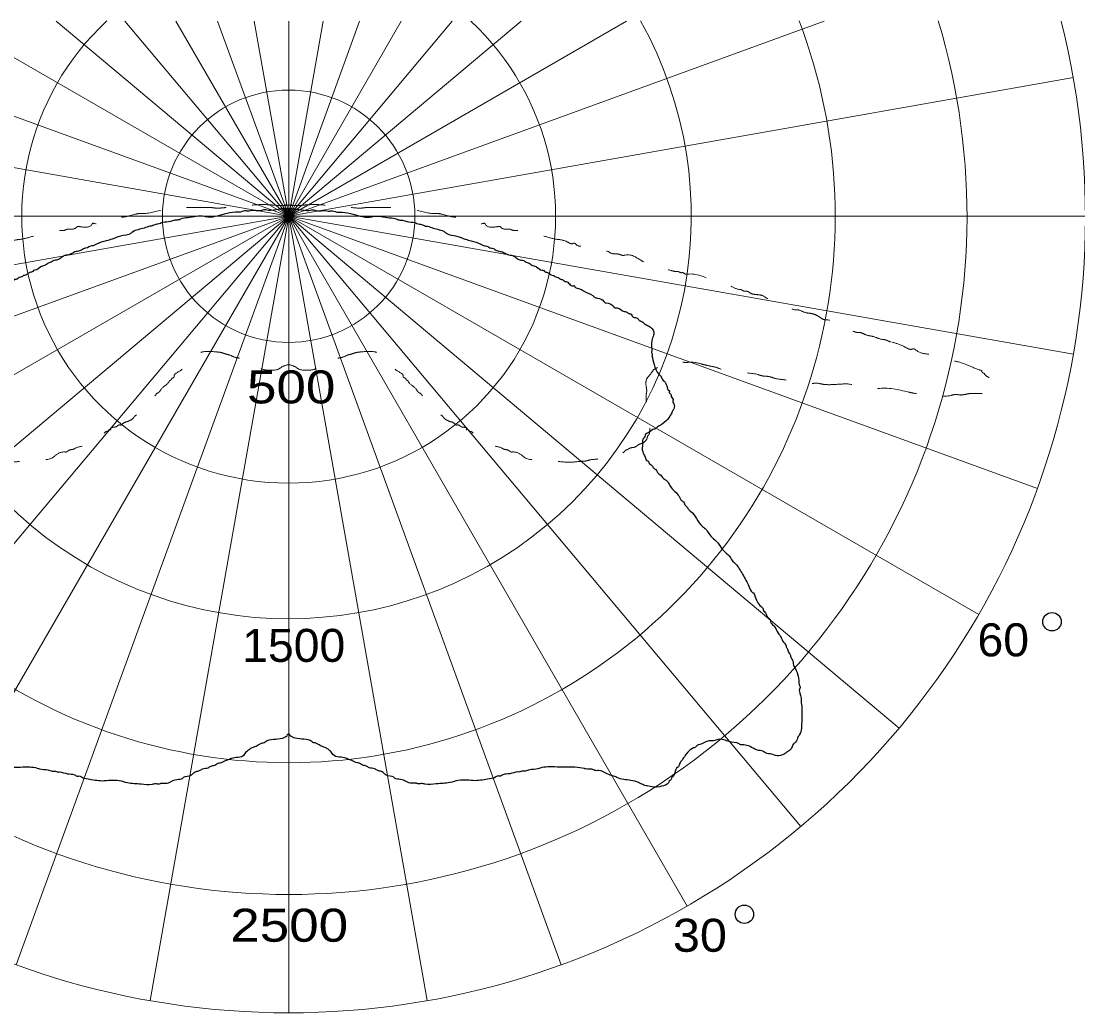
# Model space of a CAD drawing. Extents: x -39.6 to 16.1, y -17.6 to 34.
# Drawn here: x 8.272 to 12.275, y 27.093 to 30.849 of the extents above; entities that cross this region are included whole.
import ezdxf
from ezdxf.enums import TextEntityAlignment as Align

# ---------------------------------------------------------------- set-up
doc = ezdxf.new("R2010")
doc.units = 0
doc.header["$LTSCALE"] = 0.05
doc.linetypes.add('MEDIUM_DASHED', pattern=[4.5, 3, -1.5])
doc.layers.add('1', color=7, linetype='Continuous', lineweight=13)

msp = doc.modelspace()

# ---------------------------------------------------------------- linework, layer by layer
at = {"layer": '1'}
for p, q in [((9.28579, 30.11042), (7.25679, 30.84942)), ((9.28579, 30.11042), (8.00579, 30.84942)), ((9.28579, 30.11042), (8.40479, 30.84942)), ((9.28579, 30.11042), (8.66579, 30.84942)), ((9.28579, 30.11042), (8.85879, 30.84942)), ((9.28579, 30.11042), (9.01679, 30.84942)), ((9.28579, 30.11042), (9.15479, 30.84942)), ((9.28579, 30.11042), (11.31379, 30.84942)), ((9.28579, 30.11042), (10.56479, 30.84942)), ((9.28579, 30.11042), (10.16579, 30.84942)), ((9.28579, 30.11042), (9.90479, 30.84942)), ((9.28579, 30.11042), (9.71179, 30.84942)), ((9.28579, 30.11042), (9.55379, 30.84942)), ((9.28579, 30.11042), (9.41579, 30.84942)), ((9.28579, 30.11042), (9.28579, 30.84942)), ((9.28579, 30.11042), (6.31379, 30.63542)), ((9.28579, 30.11042), (12.25779, 30.63542)), ((9.28579, 30.11042), (6.26779, 30.11142)), ((6.26879, 30.11042), (12.30279, 30.11042)), ((9.28579, 30.11042), (6.31379, 29.58742)), ((9.28579, 30.11042), (6.44979, 29.07942)), ((9.28579, 30.11042), (6.67179, 28.60242)), ((9.28579, 30.11042), (6.97379, 28.17142)), ((9.28579, 30.11042), (7.34579, 27.79942)), ((9.28579, 30.11042), (7.77679, 27.49742)), ((9.28579, 30.11042), (8.25379, 27.27542)), ((9.28579, 30.11042), (8.76179, 27.13942)), ((9.28579, 30.11042), (12.30379, 30.11142)), ((9.28579, 30.11042), (9.28579, 27.09342)), ((9.28579, 30.11042), (9.80979, 27.13942)), ((9.28579, 30.11042), (10.31779, 27.27542)), ((9.28579, 30.11042), (10.79479, 27.49742)), ((9.28579, 30.11042), (11.22579, 27.79942)), ((9.28579, 30.11042), (11.59779, 28.17142)), ((9.28579, 30.11042), (11.89979, 28.60242)), ((9.28579, 30.11042), (12.12179, 29.07942)), ((9.28579, 30.11042), (12.25779, 29.58742))]:
    msp.add_line(p, q, dxfattribs=at)
msp.add_circle((9.28579, 30.11042), 0.47803, dxfattribs=at)
at = {"layer": '1', "lineweight": 25}
for centre in [(12.17679, 28.57442), (11.01179, 27.46642)]:
    msp.add_circle(centre, 0.03489, dxfattribs=at)
at = {"layer": '1'}
for radius, start, end in [(3.01743, 165.81631, 14.18369), (2.56899, 163.27297, 16.73988), (2.06984, 159.06789, 20.94201), (1.5247, 150.99651, 29.03998), (1.011, 132.95316, 46.96389)]:
    msp.add_arc((9.28579, 30.11042), radius, start, end, dxfattribs=at)
at = {"layer": '1', "linetype": 'MEDIUM_DASHED'}
for points in [[(9.29779, 30.15342), (9.27279, 30.15142), (9.24179, 30.15142), (9.21679, 30.15342), (9.15779, 30.15342), (9.12579, 30.15042), (9.10679, 30.15042), (9.04679, 30.14342), (9.00979, 30.14142), (8.99079, 30.14342), (8.95279, 30.14342), (8.87979, 30.14342), (8.84379, 30.13942), (8.81879, 30.13642), (8.73379, 30.12042), (8.71779, 30.12042), (8.70679, 30.11842), (8.65979, 30.10742), (8.64479, 30.10642), (8.59179, 30.09542), (8.55179, 30.08242), (8.54179, 30.08242), (8.54079, 30.08042), (8.49879, 30.07042), (8.48279, 30.06942), (8.48079, 30.06742), (8.45379, 30.06142), (8.44779, 30.06142), (8.44079, 30.05842), (8.42079, 30.05642), (8.36379, 30.04442), (8.35779, 30.04242), (8.32979, 30.03742), (8.27379, 30.02342), (8.23479, 30.01542), (8.20779, 30.00742), (8.20579, 30.00842), (8.19479, 30.00142), (8.16579, 29.99642), (8.13579, 29.98842), (8.11779, 29.98442), (8.10179, 29.97842), (8.07279, 29.97542), (8.06879, 29.97242), (8.03979, 29.96742), (8.02279, 29.96242), (8.01879, 29.96142), (8.01479, 29.96242), (7.95479, 29.94542), (7.93679, 29.93742), (7.93179, 29.93742), (7.91679, 29.93042), (7.91279, 29.93042), (7.91079, 29.92842), (7.90079, 29.92642), (7.88979, 29.92142), (7.83879, 29.90542), (7.82079, 29.90142), (7.81279, 29.90142), (7.79779, 29.89642), (7.79079, 29.89642), (7.78879, 29.89442), (7.76979, 29.89142), (7.67679, 29.86642), (7.67379, 29.86542), (7.64179, 29.85442), (7.62079, 29.85042), (7.58079, 29.83342), (7.56979, 29.83142), (7.56579, 29.82842), (7.54479, 29.82442), (7.54079, 29.82142), (7.51179, 29.81342), (7.49279, 29.81042), (7.46179, 29.79342), (7.44279, 29.78942), (7.41479, 29.77742), (7.40279, 29.77342), (7.36979, 29.75642), (7.36179, 29.75642), (7.32779, 29.74542), (7.30379, 29.74142), (7.28679, 29.73542), (7.27779, 29.73042), (7.25479, 29.71842), (7.25079, 29.71842), (7.19279, 29.69042), (7.17179, 29.68542), (7.14679, 29.67442), (7.13279, 29.67042), (7.11979, 29.66942), (7.09979, 29.66142), (7.07079, 29.65442), (7.03579, 29.64342), (7.02279, 29.64142), (7.01479, 29.63742), (6.99979, 29.63342)], [(9.27379, 30.15342), (9.29879, 30.15142), (9.32979, 30.15142), (9.35479, 30.15342), (9.41379, 30.15342), (9.44579, 30.15042), (9.46479, 30.15042), (9.52479, 30.14342), (9.56179, 30.14142), (9.58079, 30.14342), (9.61879, 30.14342), (9.69179, 30.14342), (9.72779, 30.13942), (9.75279, 30.13642), (9.83779, 30.12042), (9.85379, 30.12042), (9.86479, 30.11842), (9.91179, 30.10742), (9.92679, 30.10642), (9.97979, 30.09542), (10.01979, 30.08242), (10.02979, 30.08242), (10.03079, 30.08042), (10.07279, 30.07042), (10.08879, 30.06942), (10.09079, 30.06742), (10.11779, 30.06142), (10.12379, 30.06142), (10.13079, 30.05842), (10.15079, 30.05642), (10.20779, 30.04442), (10.21379, 30.04242), (10.24179, 30.03742), (10.29779, 30.02342), (10.33679, 30.01542), (10.36379, 30.00742), (10.36579, 30.00842), (10.37679, 30.00142), (10.40579, 29.99642), (10.43579, 29.98842), (10.45379, 29.98442), (10.46979, 29.97842), (10.49879, 29.97542), (10.50279, 29.97242), (10.53179, 29.96742), (10.54879, 29.96242), (10.55279, 29.96142), (10.55679, 29.96242), (10.61679, 29.94542), (10.63479, 29.93742), (10.63979, 29.93742), (10.65479, 29.93042), (10.65879, 29.93042), (10.66079, 29.92842), (10.67079, 29.92642), (10.68179, 29.92142), (10.73279, 29.90542), (10.75079, 29.90142), (10.75879, 29.90142), (10.77379, 29.89642), (10.78079, 29.89642), (10.78279, 29.89442), (10.80179, 29.89142), (10.89479, 29.86642), (10.89779, 29.86542), (10.92979, 29.85442), (10.95079, 29.85042), (10.99079, 29.83342), (11.00179, 29.83142), (11.00579, 29.82842), (11.02679, 29.82442), (11.03079, 29.82142), (11.05979, 29.81342), (11.07879, 29.81042), (11.10979, 29.79342), (11.12879, 29.78942), (11.15679, 29.77742), (11.16879, 29.77342), (11.20179, 29.75642), (11.20979, 29.75642), (11.24379, 29.74542), (11.26779, 29.74142), (11.28479, 29.73542), (11.29379, 29.73042), (11.31679, 29.71842), (11.32079, 29.71842), (11.37879, 29.69042), (11.39979, 29.68542), (11.42479, 29.67442), (11.43879, 29.67042), (11.45179, 29.66942), (11.47179, 29.66142), (11.50079, 29.65442), (11.53579, 29.64342), (11.54879, 29.64142), (11.55679, 29.63742), (11.57179, 29.63342)], [(11.57179, 29.63342), (11.62079, 29.61442), (11.64779, 29.60742), (11.64979, 29.60842), (11.66279, 29.60242), (11.71079, 29.58742), (11.72279, 29.58542), (11.74679, 29.57942), (11.78679, 29.56642), (11.82279, 29.55842), (11.90079, 29.52842), (11.90479, 29.52742), (11.90679, 29.52742), (11.91479, 29.51742), (11.92079, 29.51442), (11.92179, 29.51242), (11.94579, 29.49542), (11.94879, 29.49142), (11.94779, 29.48942), (11.94979, 29.48842), (11.95279, 29.47342), (11.95479, 29.47242), (11.95379, 29.46342), (11.95079, 29.46142), (11.95079, 29.45742), (11.93079, 29.44442), (11.92379, 29.44142), (11.87679, 29.43942), (11.84679, 29.43542), (11.82779, 29.43342), (11.81379, 29.43542), (11.79379, 29.43142), (11.73779, 29.43242), (11.71479, 29.43642), (11.69479, 29.43742), (11.65679, 29.43942), (11.63379, 29.44442), (11.51579, 29.45742), (11.50779, 29.45642), (11.46579, 29.46042), (11.44279, 29.46442), (11.42779, 29.47042), (11.36079, 29.47342), (11.33179, 29.47242), (11.30679, 29.47442), (11.28279, 29.47842), (11.27279, 29.47742), (11.24979, 29.48042), (11.20479, 29.48242), (11.17279, 29.48942), (11.12779, 29.49642), (11.10279, 29.50342), (11.08179, 29.50542), (11.06379, 29.51042), (10.98079, 29.52042), (10.96179, 29.52342), (10.94179, 29.52542), (10.90679, 29.53742), (10.86979, 29.54542), (10.84679, 29.55142), (10.80079, 29.55742), (10.78879, 29.55642), (10.77379, 29.55842), (10.75879, 29.55842), (10.71279, 29.55342), (10.68979, 29.54342), (10.68479, 29.53842), (10.67479, 29.53342), (10.65579, 29.51242), (10.64079, 29.49142), (10.64079, 29.45942), (10.64179, 29.45142), (10.63979, 29.43442), (10.64379, 29.39242), (10.64879, 29.37142), (10.65279, 29.33342), (10.65279, 29.29342), (10.65079, 29.28442), (10.64679, 29.27942), (10.64279, 29.26842), (10.63179, 29.25442), (10.61179, 29.24542), (10.60179, 29.23842), (10.59079, 29.23442), (10.58279, 29.23342), (10.56979, 29.22742), (10.56179, 29.22342), (10.55779, 29.21942), (10.54379, 29.21142), (10.52879, 29.20842), (10.52379, 29.20542), (10.50079, 29.20342), (10.49479, 29.20042), (10.48579, 29.19942), (10.47979, 29.19642), (10.46879, 29.19442), (10.45479, 29.19042)], [(8.11679, 29.19042), (8.14879, 29.18642), (8.16779, 29.18242), (8.16979, 29.18242), (8.20579, 29.17942), (8.26279, 29.18142), (8.29879, 29.18542), (8.33479, 29.18742), (8.39879, 29.20142), (8.40079, 29.20342), (8.43879, 29.21742), (8.44279, 29.21742), (8.45279, 29.22342), (8.47179, 29.22842), (8.48079, 29.23342), (8.52079, 29.24742), (8.52379, 29.25142), (8.53379, 29.25842), (8.54979, 29.26342), (8.55479, 29.26742), (8.56179, 29.26942), (8.56679, 29.27342), (8.56879, 29.27442), (8.58179, 29.28242), (8.59379, 29.29442), (8.60079, 29.29642), (8.60479, 29.30042), (8.60979, 29.30242), (8.61179, 29.30142), (8.61179, 29.30442), (8.62379, 29.31142), (8.63479, 29.31442), (8.64179, 29.31942), (8.65479, 29.32142), (8.65579, 29.32342), (8.65879, 29.32642), (8.67879, 29.33442), (8.69579, 29.34442), (8.70479, 29.35442), (8.72979, 29.37442), (8.73879, 29.38642), (8.75379, 29.39942), (8.76279, 29.41042), (8.78079, 29.43242), (8.78879, 29.44042), (8.79279, 29.44242), (8.80279, 29.45542), (8.83279, 29.48442), (8.83479, 29.48742), (8.83879, 29.48942), (8.84479, 29.49742), (8.85179, 29.50142), (8.85179, 29.50342), (8.88079, 29.52942), (8.89879, 29.55342), (8.90379, 29.55642), (8.91079, 29.56542), (8.91279, 29.56542), (8.92379, 29.57942), (8.94179, 29.59142), (8.95979, 29.59642), (9.01379, 29.59642), (9.03279, 29.59342), (9.05179, 29.58742), (9.05679, 29.58642), (9.08179, 29.57642), (9.09679, 29.57342), (9.13279, 29.56242), (9.15179, 29.55242), (9.15379, 29.55342), (9.15379, 29.55142), (9.16879, 29.54542), (9.17779, 29.53742), (9.21579, 29.52742), (9.25279, 29.53442), (9.25679, 29.53742), (9.28579, 29.54842)], [(10.45479, 29.19042), (10.42279, 29.18642), (10.40379, 29.18242), (10.40179, 29.18242), (10.36579, 29.17942), (10.30879, 29.18142), (10.27279, 29.18542), (10.23679, 29.18742), (10.17279, 29.20142), (10.17079, 29.20342), (10.13279, 29.21742), (10.12879, 29.21742), (10.11879, 29.22342), (10.09979, 29.22842), (10.09079, 29.23342), (10.05079, 29.24742), (10.04779, 29.25142), (10.03779, 29.25842), (10.02179, 29.26342), (10.01679, 29.26742), (10.00979, 29.26942), (10.00479, 29.27342), (10.00279, 29.27442), (9.98979, 29.28242), (9.97779, 29.29442), (9.97079, 29.29642), (9.96679, 29.30042), (9.96179, 29.30242), (9.95979, 29.30142), (9.95979, 29.30442), (9.94779, 29.31142), (9.93679, 29.31442), (9.92979, 29.31942), (9.91679, 29.32142), (9.91579, 29.32342), (9.91279, 29.32642), (9.89279, 29.33442), (9.87579, 29.34442), (9.86679, 29.35442), (9.84179, 29.37442), (9.83279, 29.38642), (9.81779, 29.39942), (9.80879, 29.41042), (9.79079, 29.43242), (9.78279, 29.44042), (9.77879, 29.44242), (9.76879, 29.45542), (9.73879, 29.48442), (9.73679, 29.48742), (9.73279, 29.48942), (9.72679, 29.49742), (9.71979, 29.50142), (9.71979, 29.50342), (9.69079, 29.52942), (9.67279, 29.55342), (9.66779, 29.55642), (9.66079, 29.56542), (9.65879, 29.56542), (9.64779, 29.57942), (9.62979, 29.59142), (9.61179, 29.59642), (9.55779, 29.59642), (9.53879, 29.59342), (9.51979, 29.58742), (9.51479, 29.58642), (9.48979, 29.57642), (9.47479, 29.57342), (9.43879, 29.56242), (9.41979, 29.55242), (9.41779, 29.55342), (9.41779, 29.55142), (9.40279, 29.54542), (9.39379, 29.53742), (9.35579, 29.52742), (9.31879, 29.53442), (9.31479, 29.53742), (9.28579, 29.54842)]]:
    msp.add_spline(points, degree=3, dxfattribs=at)
at = {"layer": '1', "lineweight": 25}
for points in [[(9.29679, 30.13842), (9.24579, 30.13642), (9.20979, 30.13242), (9.19879, 30.13442), (9.16679, 30.13042), (9.15279, 30.13242), (9.13079, 30.12942), (9.12579, 30.13042), (9.10379, 30.12642), (9.08379, 30.12542), (9.04179, 30.11842), (8.97079, 30.10842), (8.96679, 30.10942), (8.90379, 30.10442), (8.87579, 30.09942), (8.87179, 30.09742), (8.85479, 30.09542), (8.83779, 30.09042), (8.80879, 30.08642), (8.79079, 30.08042), (8.78279, 30.07942), (8.76779, 30.07342), (8.75979, 30.07242), (8.73879, 30.06542), (8.69379, 30.05042), (8.68879, 30.04642), (8.64879, 30.03542), (8.61679, 30.02342), (8.59479, 30.01742), (8.55779, 30.00442), (8.54779, 29.99942), (8.54079, 29.99842), (8.51779, 29.98942), (8.51179, 29.98842), (8.49779, 29.98042), (8.48079, 29.97642), (8.47179, 29.97342), (8.45279, 29.96442), (8.44179, 29.96242), (8.42779, 29.95642), (8.41979, 29.95042), (8.40679, 29.94442), (8.39579, 29.94242), (8.38979, 29.93842), (8.37479, 29.93242), (8.36879, 29.92742), (8.36079, 29.92342), (8.34679, 29.91842), (8.32579, 29.90642), (8.32279, 29.90642), (8.31679, 29.90142), (8.30579, 29.89742), (8.28579, 29.88642), (8.28079, 29.88542), (8.27779, 29.88242), (8.26179, 29.87642), (8.25779, 29.87242), (8.24779, 29.87042), (8.23979, 29.86342), (8.23479, 29.86342), (8.22279, 29.85442), (8.20679, 29.84742), (8.20279, 29.84742), (8.20279, 29.84542), (8.19279, 29.83842), (8.17679, 29.83242), (8.16979, 29.82742), (8.13379, 29.81042), (8.12279, 29.80142), (8.11579, 29.80042), (8.09179, 29.78742), (8.08979, 29.78442), (8.08279, 29.78242), (8.05679, 29.76942), (8.05279, 29.76442), (8.04179, 29.76342), (8.01479, 29.74942), (8.00779, 29.74842), (7.99679, 29.74142), (7.99379, 29.74042), (7.99179, 29.74042), (7.98179, 29.72942), (7.96379, 29.72342), (7.95579, 29.71442), (7.95179, 29.71342), (7.93779, 29.70242), (7.92279, 29.69542), (7.91579, 29.69042), (7.90779, 29.68242), (7.90379, 29.67542), (7.90379, 29.65942), (7.90779, 29.64942), (7.91079, 29.60642), (7.91079, 29.60142), (7.91079, 29.59042), (7.90879, 29.58442), (7.90979, 29.58242)], [(9.27479, 30.13842), (9.32579, 30.13642), (9.36179, 30.13242), (9.37279, 30.13442), (9.40479, 30.13042), (9.41879, 30.13242), (9.44079, 30.12942), (9.44579, 30.13042), (9.46779, 30.12642), (9.48779, 30.12542), (9.52979, 30.11842), (9.60079, 30.10842), (9.60479, 30.10942), (9.66779, 30.10442), (9.69579, 30.09942), (9.69979, 30.09742), (9.71679, 30.09542), (9.73379, 30.09042), (9.76279, 30.08642), (9.78079, 30.08042), (9.78879, 30.07942), (9.80379, 30.07342), (9.81179, 30.07242), (9.83279, 30.06542), (9.87779, 30.05042), (9.88279, 30.04642), (9.92279, 30.03542), (9.95479, 30.02342), (9.97679, 30.01742), (10.01379, 30.00442), (10.02379, 29.99942), (10.03079, 29.99842), (10.05379, 29.98942), (10.05979, 29.98842), (10.07379, 29.98042), (10.09079, 29.97642), (10.09979, 29.97342), (10.11879, 29.96442), (10.12979, 29.96242), (10.14379, 29.95642), (10.15179, 29.95042), (10.16479, 29.94442), (10.17579, 29.94242), (10.18179, 29.93842), (10.19679, 29.93242), (10.20279, 29.92742), (10.21079, 29.92342), (10.22479, 29.91842), (10.24579, 29.90642), (10.24879, 29.90642), (10.25479, 29.90142), (10.26579, 29.89742), (10.28579, 29.88642), (10.29079, 29.88542), (10.29379, 29.88242), (10.30979, 29.87642), (10.31379, 29.87242), (10.32379, 29.87042), (10.33179, 29.86342), (10.33679, 29.86342), (10.34879, 29.85442), (10.36479, 29.84742), (10.36879, 29.84742), (10.36879, 29.84542), (10.37879, 29.83842), (10.39479, 29.83242), (10.40179, 29.82742), (10.43779, 29.81042), (10.44879, 29.80142), (10.45579, 29.80042), (10.47979, 29.78742), (10.48179, 29.78442), (10.48879, 29.78242), (10.51479, 29.76942), (10.51879, 29.76442), (10.52979, 29.76342), (10.55679, 29.74942), (10.56379, 29.74842), (10.57479, 29.74142), (10.57779, 29.74042), (10.57979, 29.74042), (10.58979, 29.72942), (10.60779, 29.72342), (10.61579, 29.71442), (10.61979, 29.71342), (10.63379, 29.70242), (10.64879, 29.69542), (10.65579, 29.69042), (10.66379, 29.68242), (10.66779, 29.67542), (10.66779, 29.65942), (10.66379, 29.64942), (10.66079, 29.60642), (10.66079, 29.60142), (10.66079, 29.59042), (10.66279, 29.58442), (10.66179, 29.58242)], [(10.66179, 29.58242), (10.66979, 29.54942), (10.68779, 29.51242), (10.69479, 29.50542), (10.70179, 29.49142), (10.70779, 29.48542), (10.71779, 29.46842), (10.71979, 29.46042), (10.72579, 29.45042), (10.72779, 29.44942), (10.72679, 29.44442), (10.73379, 29.43542), (10.73479, 29.43142), (10.73479, 29.42742), (10.74179, 29.41242), (10.74079, 29.41042), (10.74579, 29.39542), (10.74179, 29.37642), (10.73479, 29.36242), (10.72679, 29.34942), (10.70079, 29.32342), (10.68279, 29.31242), (10.67279, 29.30442), (10.66479, 29.30242), (10.64379, 29.28842), (10.63979, 29.28742), (10.63279, 29.27242), (10.63079, 29.27042), (10.62579, 29.24642), (10.62479, 29.23342), (10.62679, 29.21742), (10.63579, 29.19842), (10.64479, 29.18442), (10.64679, 29.18442), (10.64979, 29.17642), (10.66179, 29.16642), (10.66479, 29.16042), (10.67879, 29.14742), (10.68079, 29.14242), (10.69279, 29.13142), (10.69479, 29.12942), (10.70879, 29.11442), (10.71579, 29.11042), (10.72479, 29.09942), (10.73479, 29.08242), (10.75279, 29.06342), (10.76579, 29.04642), (10.77079, 29.03642), (10.78079, 29.02842), (10.78879, 29.01442), (10.79579, 29.00742), (10.79979, 29.00042), (10.80779, 28.99342), (10.85279, 28.93542), (10.86779, 28.92242), (10.88079, 28.90342), (10.89979, 28.88442), (10.92279, 28.85742), (10.92779, 28.84942), (10.94879, 28.82942), (10.95379, 28.82442), (10.96579, 28.80642), (10.97779, 28.79442), (11.00479, 28.75442), (11.01779, 28.73142), (11.02879, 28.70942), (11.04279, 28.68542), (11.04579, 28.68342), (11.05279, 28.66842), (11.07979, 28.62742), (11.08179, 28.62542), (11.08279, 28.61842), (11.08979, 28.61142), (11.09679, 28.59542), (11.11079, 28.57842), (11.11079, 28.57542), (11.11579, 28.56642), (11.12679, 28.55442), (11.13979, 28.53142), (11.15079, 28.51442), (11.15579, 28.50242), (11.16979, 28.48242), (11.17079, 28.47742), (11.17379, 28.47342), (11.17879, 28.45942), (11.18379, 28.45242), (11.18779, 28.44042), (11.18979, 28.43542), (11.19379, 28.42942), (11.19779, 28.41042), (11.20179, 28.40242), (11.21779, 28.34642), (11.21879, 28.33642), (11.22279, 28.32442), (11.22179, 28.32242), (11.22679, 28.28542), (11.22679, 28.26642)], [(7.34479, 28.26642), (7.34279, 28.25442), (7.34279, 28.20142), (7.35179, 28.14542), (7.35579, 28.13942), (7.36579, 28.11842), (7.37379, 28.11142), (7.38079, 28.09642), (7.39279, 28.08442), (7.40979, 28.07342), (7.43579, 28.06642), (7.46279, 28.07442), (7.47379, 28.07542), (7.48979, 28.08442), (7.51179, 28.08842), (7.52079, 28.09242), (7.56879, 28.10842), (7.57379, 28.10842), (7.57979, 28.11142), (7.61779, 28.12042), (7.63779, 28.12742), (7.66779, 28.12642), (7.67679, 28.12342), (7.69779, 28.12242), (7.72879, 28.10942), (7.73679, 28.10742), (7.74279, 28.10142), (7.75279, 28.09642), (7.77479, 28.07942), (7.79879, 28.04642), (7.80679, 28.03242), (7.80979, 28.02442), (7.81179, 28.02342), (7.82379, 28.00242), (7.82879, 27.98942), (7.83379, 27.98642), (7.83779, 27.97542), (7.84479, 27.97042), (7.84779, 27.96442), (7.87379, 27.95142), (7.88179, 27.94942), (7.92779, 27.95242), (7.94479, 27.95742), (7.96079, 27.96542), (7.98979, 27.97342), (8.04279, 27.98442), (8.05079, 27.98842), (8.06779, 27.99342), (8.08979, 28.00342), (8.11079, 28.01042), (8.12579, 28.01142), (8.12979, 28.01342), (8.16179, 28.01742), (8.16579, 28.01842), (8.23779, 28.02342), (8.27879, 28.02442), (8.30479, 28.02442), (8.33379, 28.02042), (8.34179, 28.01742), (8.37379, 28.01342), (8.38979, 28.00842), (8.40679, 28.00742), (8.41179, 28.00542), (8.41779, 28.00542), (8.44779, 27.99842), (8.47479, 27.99442), (8.48679, 27.98942), (8.49179, 27.99042), (8.50079, 27.98642), (8.52579, 27.97942), (8.57979, 27.97242), (8.61079, 27.97442), (8.64379, 27.97342), (8.67479, 27.96542), (8.72679, 27.96042), (8.76979, 27.95942), (8.78379, 27.96142), (8.79979, 27.96142), (8.80179, 27.96242), (8.81979, 27.96242), (8.86179, 27.97742), (8.88479, 27.98242), (8.88779, 27.98542), (8.91679, 27.99342), (8.92179, 27.99742), (8.93479, 28.00742), (8.94779, 28.01042), (8.95979, 28.01742), (8.98079, 28.02142), (8.99179, 28.02742), (9.00579, 28.03142), (9.02279, 28.04042), (9.02579, 28.04042), (9.04679, 28.04942), (9.05379, 28.05142), (9.06879, 28.05742), (9.09379, 28.06142)], [(11.22679, 28.26642), (11.22879, 28.25442), (11.22879, 28.20142), (11.21979, 28.14542), (11.21579, 28.13942), (11.20579, 28.11842), (11.19779, 28.11142), (11.19079, 28.09642), (11.17879, 28.08442), (11.16179, 28.07342), (11.13579, 28.06642), (11.10879, 28.07442), (11.09779, 28.07542), (11.08179, 28.08442), (11.05979, 28.08842), (11.05079, 28.09242), (11.00279, 28.10842), (10.99779, 28.10842), (10.99179, 28.11142), (10.95379, 28.12042), (10.93379, 28.12742), (10.90379, 28.12642), (10.89479, 28.12342), (10.87379, 28.12242), (10.84279, 28.10942), (10.83479, 28.10742), (10.82879, 28.10142), (10.81879, 28.09642), (10.79679, 28.07942), (10.77279, 28.04642), (10.76479, 28.03242), (10.76179, 28.02442), (10.75979, 28.02342), (10.74779, 28.00242), (10.74279, 27.98942), (10.73779, 27.98642), (10.73379, 27.97542), (10.72679, 27.97042), (10.72379, 27.96442), (10.69779, 27.95142), (10.68979, 27.94942), (10.64379, 27.95242), (10.62679, 27.95742), (10.61079, 27.96542), (10.58179, 27.97342), (10.52879, 27.98442), (10.52079, 27.98842), (10.50379, 27.99342), (10.48179, 28.00342), (10.46079, 28.01042), (10.44579, 28.01142), (10.44179, 28.01342), (10.40979, 28.01742), (10.40579, 28.01842), (10.33379, 28.02342), (10.29279, 28.02442), (10.26679, 28.02442), (10.23779, 28.02042), (10.22979, 28.01742), (10.19779, 28.01342), (10.18179, 28.00842), (10.16479, 28.00742), (10.15979, 28.00542), (10.15379, 28.00542), (10.12379, 27.99842), (10.09679, 27.99442), (10.08479, 27.98942), (10.07979, 27.99042), (10.07079, 27.98642), (10.04579, 27.97942), (9.99179, 27.97242), (9.96079, 27.97442), (9.92779, 27.97342), (9.89679, 27.96542), (9.84479, 27.96042), (9.80179, 27.95942), (9.78779, 27.96142), (9.77179, 27.96142), (9.76979, 27.96242), (9.75179, 27.96242), (9.70979, 27.97742), (9.68679, 27.98242), (9.68379, 27.98542), (9.65479, 27.99342), (9.64979, 27.99742), (9.63679, 28.00742), (9.62379, 28.01042), (9.61179, 28.01742), (9.59079, 28.02142), (9.57979, 28.02742), (9.56579, 28.03142), (9.54879, 28.04042), (9.54579, 28.04042), (9.52479, 28.04942), (9.51779, 28.05142), (9.50279, 28.05742), (9.47779, 28.06142)], [(9.09379, 28.06142), (9.11879, 28.07142), (9.12379, 28.07942), (9.13679, 28.09142), (9.14779, 28.09842), (9.15779, 28.10142), (9.17479, 28.11042), (9.18579, 28.11542), (9.19079, 28.11542), (9.19679, 28.11942), (9.26179, 28.13342), (9.27079, 28.13742), (9.27479, 28.13942), (9.27679, 28.13942), (9.28179, 28.14742), (9.28479, 28.14942)], [(9.47779, 28.06142), (9.45279, 28.07142), (9.44779, 28.07942), (9.43479, 28.09142), (9.42379, 28.09842), (9.41379, 28.10142), (9.39679, 28.11042), (9.38579, 28.11542), (9.38079, 28.11542), (9.37479, 28.11942), (9.30979, 28.13342), (9.30079, 28.13742), (9.29679, 28.13942), (9.29479, 28.13942), (9.28979, 28.14742), (9.28579, 28.14942)]]:
    msp.add_spline(points, degree=3, dxfattribs=at)

# ---------------------------------------------------------------- texts
at = {"layer": '1'}
for s, width, p in [('500', 1.2, (9.29529, 29.40142)), ('1500', 1.05, (9.30479, 28.42242)), ('60', 1.05, (11.99229, 28.44342)), ('2500', 1.2, (9.28779, 27.36242)), ('30', 1.1, (10.84329, 27.32442))]:
    msp.add_text(s, height=0.125, dxfattribs=dict(at, width=width)).set_placement(p, align=Align.CENTER)

doc.saveas('drawing.dxf')
